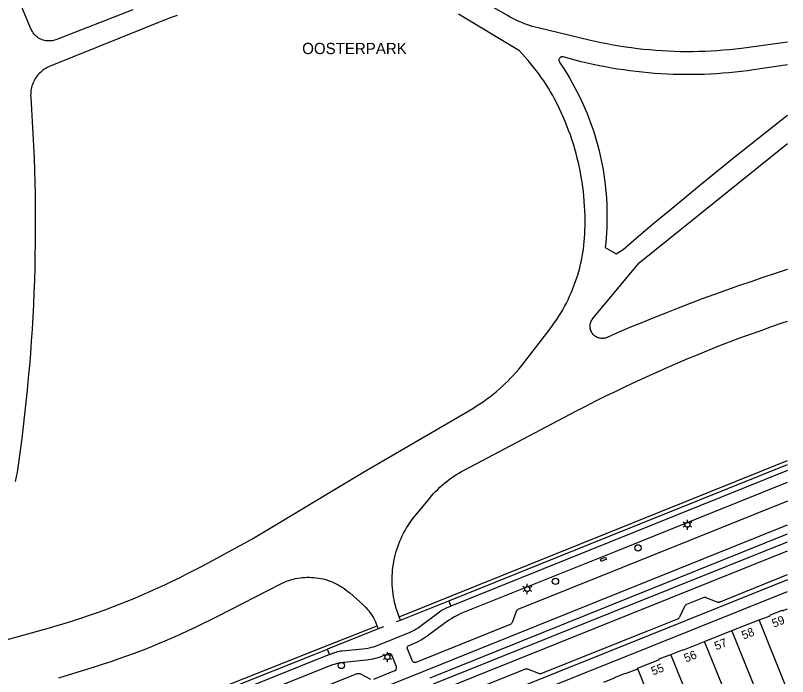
# Model space of a CAD drawing. Extents: x 122462 to 123306, y 485548 to 486417.
# Drawn here: x 123168.9 to 123306, y 485776.1 to 485893.5 of the extents above; entities that cross this region are included whole.
import ezdxf

# ---------------------------------------------------------------- set-up
doc = ezdxf.new("R2010")
doc.units = 0
for name, color, linetype in [('B-WE-IE-MEUBILAIR_WEGMEUBILAIR_VERKEERSBORD-S', 7, 'Continuous'), ('Level 1', 7, 'Continuous'), ('Level 17', 7, 'Continuous'), ('Level 19', 7, 'Continuous'), ('Level 37', 7, 'Continuous'), ('Level 4', 7, 'Continuous'), ('Level 40', 7, 'Continuous'), ('Level 50', 7, 'Continuous'), ('Level 53', 7, 'Continuous'), ('N werkgrens', 7, 'Continuous'), ('N-WE-AL-T25', 7, 'Continuous'), ('N-WE-GR-BOOM_DOORWORTELBARE RUIMTE-G', 7, 'Continuous')]:
    doc.layers.add(name, color=color, linetype=linetype)

msp = doc.modelspace()

# ---------------------------------------------------------------- linework, layer by layer
at = {"layer": 'Level 1'}
msp.add_line((123291.29, 485782.32), (123296.14, 485784.24), dxfattribs=at)
for points in [[(123300.99, 485786.12), (123302.91, 485786.88), (123302.87, 485786.98), (123305.04, 485787.84), (123305.08, 485787.74), (123306.02, 485788.12)], [(123296.14, 485784.24), (123300.98, 485786.15), (123300.99, 485786.12)], [(123285.3, 485780.01), (123287.37, 485780.83), (123287.41, 485780.74), (123291.29, 485782.32)], [(123279.43, 485777.45), (123279.38, 485777.56), (123283.27, 485779.1), (123283.23, 485779.19), (123285.3, 485780.01)], [(123273.37, 485775.07), (123275.3, 485775.83), (123275.26, 485775.92), (123277.21, 485776.69), (123277.25, 485776.6), (123279.43, 485777.45)]]:
    msp.add_lwpolyline(points, dxfattribs=at)
at = {"layer": 'Level 17'}
for p, q in [((123237.27, 485786.09), (123245.85, 485789.52)), ((123245.85, 485789.52), (123246.19, 485788.59)), ((123236.59, 485785.82), (123237.27, 485786.09)), ((123233.31, 485784.52), (123224.29, 485780.91)), ((123234.25, 485784.9), (123233.31, 485784.52)), ((123224.69, 485779.98), (123224.29, 485780.91))]:
    msp.add_line(p, q, dxfattribs=at)
for points in [[(123245.85, 485789.52), (123274.49, 485801.04), (123306.02, 485813.71)], [(123306.02, 485812.64), (123274.86, 485800.11), (123246.19, 485788.59)], [(123239.82, 485778.55), (123239.73, 485778.55), (123239.65, 485778.57), (123239.57, 485778.61), (123239.5, 485778.66), (123239.44, 485778.72), (123239.39, 485778.79), (123238.51, 485780.97), (123238.49, 485781.05), (123238.48, 485781.13), (123238.49, 485781.22), (123238.51, 485781.3), (123238.55, 485781.37), (123238.6, 485781.44), (123238.65, 485781.5), (123238.72, 485781.55), (123238.8, 485781.59), (123239.79, 485781.97), (123240.18, 485782.17), (123240.56, 485782.37), (123240.94, 485782.59), (123241.31, 485782.82), (123241.67, 485783.05), (123242.03, 485783.3), (123245.46, 485785.87), (123245.9, 485786.15), (123246.32, 485786.4), (123246.75, 485786.65), (123247.19, 485786.88), (123247.63, 485787.1), (123248.07, 485787.31), (123275.56, 485798.36), (123306.02, 485810.6)], [(123306.02, 485807.22), (123276.73, 485795.44), (123258.14, 485787.97), (123258.06, 485787.93), (123257.99, 485787.88), (123257.93, 485787.82), (123257.87, 485787.75), (123257.83, 485787.68), (123257.79, 485787.6), (123257.1, 485785.69), (123257.06, 485785.6), (123257, 485785.52), (123256.93, 485785.44), (123256.85, 485785.37), (123256.76, 485785.32), (123239.98, 485778.58), (123239.9, 485778.56), (123239.82, 485778.55)], [(123259.86, 485777.43), (123259.95, 485777.4), (123261.81, 485776.65), (123261.91, 485776.62), (123262.01, 485776.6), (123262.11, 485776.6), (123262.21, 485776.61), (123262.31, 485776.62), (123262.4, 485776.66), (123281.22, 485784.21), (123286.53, 485786.34), (123286.62, 485786.39), (123286.7, 485786.45), (123286.78, 485786.52), (123286.84, 485786.6), (123286.9, 485786.68), (123286.95, 485786.77), (123287.79, 485788.58), (123287.84, 485788.67), (123287.9, 485788.75), (123287.97, 485788.83), (123288.06, 485788.89), (123288.15, 485788.93), (123291.1, 485790.11), (123291.19, 485790.14), (123291.28, 485790.15), (123291.36, 485790.15), (123291.45, 485790.14), (123291.53, 485790.11), (123293.47, 485789.34), (123293.56, 485789.31), (123293.66, 485789.29), (123293.76, 485789.29), (123293.86, 485789.3), (123293.95, 485789.32), (123294.04, 485789.36), (123306.02, 485794.17)], [(123306.02, 485793.23), (123281.54, 485783.41), (123199.54, 485750.48), (123092.05, 485707.28), (123051.43, 485690.97), (123010.46, 485674.56), (123010.38, 485674.54), (123010.31, 485674.53), (123010.23, 485674.54)], [(123010.9, 485672.76), (123016.12, 485674.9), (123023.42, 485677.77), (123052.25, 485689.33), (123092.64, 485705.53), (123175.87, 485738.97), (123200.14, 485748.71), (123282.24, 485781.66), (123306.02, 485791.2)], [(123224.69, 485779.98), (123225.6, 485780.34), (123225.85, 485780.42), (123226.11, 485780.5), (123226.38, 485780.56), (123226.64, 485780.61), (123226.91, 485780.64), (123231.11, 485781.08), (123231.45, 485781.13), (123231.8, 485781.19), (123232.15, 485781.27), (123232.49, 485781.37), (123232.82, 485781.47), (123233.15, 485781.59), (123238.97, 485783.93), (123239.34, 485784.11), (123239.7, 485784.31), (123240.05, 485784.52), (123240.4, 485784.74), (123240.74, 485784.98), (123244.19, 485787.57), (123244.52, 485787.78), (123244.86, 485787.98), (123245.2, 485788.17), (123245.56, 485788.34), (123246.19, 485788.59)], [(123033.3, 485704.16), (123033.55, 485703.56), (123043.09, 485707.71), (123057.87, 485714.13), (123066.6, 485717.66), (123085.63, 485725.38), (123105.66, 485733.48), (123130.67, 485743.46), (123153.55, 485752.61), (123177.38, 485762.27), (123193.41, 485768.64), (123221.97, 485779.99), (123224.29, 485780.91)], [(123224.69, 485779.98), (123193.77, 485767.58)], [(123232.54, 485775.62), (123236.28, 485777.12), (123236.36, 485777.17), (123236.43, 485777.22), (123236.49, 485777.29), (123236.53, 485777.36), (123236.56, 485777.44), (123236.58, 485777.53), (123236.58, 485777.61), (123236.57, 485777.7), (123236.54, 485777.78), (123235.73, 485779.84), (123235.69, 485779.92), (123235.63, 485779.98), (123235.57, 485780.04), (123235.49, 485780.08), (123235.41, 485780.11), (123235.33, 485780.13), (123235.24, 485780.13), (123235.16, 485780.12), (123235.08, 485780.09), (123234.15, 485779.73), (123233.8, 485779.59), (123233.44, 485779.47), (123233.08, 485779.36), (123232.72, 485779.25), (123232.35, 485779.17), (123231.98, 485779.09), (123231.61, 485779.03), (123231.24, 485778.98), (123227.8, 485778.63), (123227.41, 485778.59), (123227.02, 485778.55), (123226.63, 485778.49), (123226.24, 485778.42), (123225.86, 485778.33), (123225.48, 485778.23), (123225.05, 485778.1), (123194.37, 485765.79)], [(123249.16, 485773.29), (123259.37, 485777.38), (123259.47, 485777.42), (123259.56, 485777.44), (123259.66, 485777.45), (123259.76, 485777.44), (123259.86, 485777.43)], [(123195.37, 485762.82), (123229.6, 485776.59), (123229.71, 485776.61), (123229.83, 485776.62), (123229.95, 485776.61), (123230.07, 485776.59), (123230.18, 485776.55), (123231.95, 485775.63)]]:
    msp.add_lwpolyline(points, dxfattribs=at)
at = {"layer": 'Level 19'}
msp.add_line((123237.27, 485786.09), (123237.02, 485786.68), dxfattribs=at)
for points in [[(123306.02, 485888.72), (123297.86, 485887.63), (123296.78, 485887.51), (123295.7, 485887.39), (123294.61, 485887.3), (123293.52, 485887.21), (123292.44, 485887.15), (123291.35, 485887.1), (123290.26, 485887.06), (123289.17, 485887.04), (123288.08, 485887.04), (123286.99, 485887.05), (123285.9, 485887.08), (123284.81, 485887.12), (123283.72, 485887.18), (123282.64, 485887.26), (123281.55, 485887.35), (123280.46, 485887.45), (123279.38, 485887.58), (123278.3, 485887.71), (123277.22, 485887.87), (123276.14, 485888.03), (123275.07, 485888.22), (123274, 485888.42), (123272.93, 485888.63), (123271.87, 485888.86), (123270.8, 485889.11), (123261.71, 485891.28), (123261.19, 485891.41), (123260.68, 485891.55), (123260.17, 485891.71), (123259.66, 485891.88), (123259.16, 485892.07), (123258.66, 485892.27), (123258.17, 485892.48), (123257.69, 485892.7), (123257.21, 485892.94), (123256.73, 485893.19), (123256.27, 485893.46), (123246.28, 485899.29)], [(123174.05, 485889.04), (123173.83, 485889.1), (123173.62, 485889.17), (123173.41, 485889.26), (123173.21, 485889.36), (123173.01, 485889.48), (123172.82, 485889.61), (123172.64, 485889.75), (123172.47, 485889.9), (123172.32, 485890.06), (123172.17, 485890.24), (123172.03, 485890.42), (123171.91, 485890.61), (123171.8, 485890.81), (123171.71, 485891.02), (123170.04, 485894.93), (123169.59, 485894.89), (123169.22, 485898.92)], [(123189.76, 485894.48), (123176.06, 485889.18), (123175.85, 485889.1), (123175.63, 485889.04), (123175.41, 485888.99), (123175.18, 485888.96), (123174.96, 485888.95), (123174.73, 485888.95), (123174.5, 485888.96), (123174.28, 485888.99), (123174.05, 485889.04)], [(123265.08, 485877.81), (123264.68, 485878.57), (123264.32, 485879.24), (123263.94, 485879.91), (123263.54, 485880.56), (123263.14, 485881.21), (123262.72, 485881.85), (123262.28, 485882.48), (123261.84, 485883.1), (123261.38, 485883.72), (123260.91, 485884.32), (123260.43, 485884.91), (123259.94, 485885.5), (123259.43, 485886.07), (123258.91, 485886.64), (123258.39, 485887.19), (123247.56, 485893.72)], [(123197.62, 485893.5), (123196.55, 485893.1), (123195.5, 485892.68), (123175.04, 485884.46), (123174.77, 485884.35), (123174.51, 485884.22), (123174.26, 485884.08), (123174.02, 485883.92), (123173.78, 485883.75), (123173.56, 485883.57), (123173.34, 485883.38), (123173.13, 485883.18), (123172.94, 485882.97), (123172.76, 485882.74), (123172.58, 485882.51), (123172.42, 485882.27), (123172.28, 485882.02), (123172.15, 485881.77), (123172.03, 485881.5), (123171.92, 485881.23), (123171.83, 485880.96), (123171.75, 485880.68), (123171.69, 485880.4), (123171.64, 485880.11), (123171.61, 485879.83), (123171.6, 485879.54), (123171.59, 485879.25), (123171.61, 485878.96), (123171.76, 485876.8), (123171.89, 485874.63), (123172.01, 485872.47)], [(123306.02, 485884.7), (123299.99, 485883.82), (123298.9, 485883.66), (123297.8, 485883.53), (123296.71, 485883.4), (123295.61, 485883.3), (123294.51, 485883.21), (123293.42, 485883.13), (123292.32, 485883.07), (123291.21, 485883.02), (123290.11, 485882.99), (123289.01, 485882.97), (123287.91, 485882.97), (123286.81, 485882.98), (123285.71, 485883.01), (123284.61, 485883.06), (123283.51, 485883.12), (123282.41, 485883.19), (123281.31, 485883.28), (123280.21, 485883.39), (123279.12, 485883.51), (123278.02, 485883.64), (123276.93, 485883.8), (123275.84, 485883.96), (123274.75, 485884.14), (123273.67, 485884.34), (123272.59, 485884.55), (123271.51, 485884.77), (123270.44, 485885.01), (123269.36, 485885.27), (123268.3, 485885.54), (123267.23, 485885.82), (123266.17, 485886.12), (123266.07, 485886.14), (123265.98, 485886.15), (123265.88, 485886.13), (123265.79, 485886.1), (123265.7, 485886.06), (123265.62, 485886.01), (123265.55, 485885.94), (123265.49, 485885.86), (123265.45, 485885.77), (123265.42, 485885.68), (123265.4, 485885.58), (123265.41, 485885.48), (123265.43, 485885.39), (123265.46, 485885.29), (123265.51, 485885.21), (123265.99, 485884.49), (123266.46, 485883.76), (123266.91, 485883.02), (123267.35, 485882.28), (123267.78, 485881.52), (123268.2, 485880.76), (123268.6, 485879.99), (123268.99, 485879.22), (123269.36, 485878.44), (123269.72, 485877.65), (123270.07, 485876.86), (123270.4, 485876.06), (123270.72, 485875.25), (123271.02, 485874.44), (123271.31, 485873.62), (123271.59, 485872.8), (123271.85, 485871.97), (123272.09, 485871.14), (123272.32, 485870.3), (123272.54, 485869.46), (123272.74, 485868.62), (123272.92, 485867.78), (123273.09, 485866.93), (123273.25, 485866.07), (123273.39, 485865.22), (123273.51, 485864.36), (123273.62, 485863.5), (123273.71, 485862.64), (123273.79, 485861.78), (123273.85, 485860.91), (123273.9, 485860.05), (123273.94, 485859.18), (123273.95, 485858.31), (123273.95, 485857.45), (123273.94, 485856.58), (123273.91, 485855.71), (123273.87, 485854.85), (123273.81, 485853.98), (123273.73, 485853.12), (123273.64, 485852.26), (123275.55, 485851.15)], [(123154.79, 485779.15), (123174.92, 485784.73), (123176.32, 485785.13), (123177.72, 485785.55), (123179.11, 485785.98), (123180.5, 485786.43), (123181.89, 485786.9), (123183.26, 485787.38), (123184.64, 485787.87), (123186.01, 485788.38), (123187.37, 485788.91), (123188.73, 485789.45), (123190.08, 485790), (123191.42, 485790.57), (123192.76, 485791.15), (123194.09, 485791.75), (123195.42, 485792.36), (123196.74, 485792.99), (123198.05, 485793.63), (123199.35, 485794.29), (123200.65, 485794.96), (123201.94, 485795.64), (123210.86, 485800.44), (123230.61, 485812.33), (123250.12, 485823.7), (123250.74, 485824.08), (123251.35, 485824.48), (123251.95, 485824.88), (123252.54, 485825.31), (123253.12, 485825.74), (123253.69, 485826.19), (123254.25, 485826.65), (123254.81, 485827.12), (123255.35, 485827.6), (123255.88, 485828.1), (123256.4, 485828.6), (123256.9, 485829.12), (123257.4, 485829.65), (123257.88, 485830.19), (123258.36, 485830.74), (123258.82, 485831.3), (123259.26, 485831.87), (123263.85, 485837.85), (123264.25, 485838.39), (123264.64, 485838.93), (123265.02, 485839.49), (123265.39, 485840.06), (123265.74, 485840.63), (123266.08, 485841.21), (123266.41, 485841.8), (123266.73, 485842.39), (123267.03, 485843), (123267.31, 485843.61), (123267.59, 485844.22), (123267.85, 485844.84), (123268.09, 485845.47), (123268.32, 485846.1), (123268.54, 485846.74), (123268.75, 485847.38), (123268.93, 485848.03), (123269.11, 485848.68), (123269.27, 485849.33), (123269.41, 485849.99), (123269.54, 485850.65), (123269.66, 485851.31), (123269.76, 485851.98), (123269.84, 485852.65), (123269.91, 485853.32), (123269.97, 485853.99), (123270.01, 485854.66), (123270.03, 485855.33), (123270.05, 485856.19), (123270.06, 485857.06), (123270.05, 485857.92), (123270.02, 485858.78), (123269.98, 485859.64), (123269.92, 485860.5), (123269.84, 485861.36), (123269.75, 485862.21), (123269.64, 485863.07), (123269.52, 485863.92), (123269.38, 485864.77), (123269.23, 485865.62), (123269.06, 485866.46), (123268.87, 485867.3), (123268.67, 485868.14), (123268.46, 485868.97), (123268.22, 485869.8), (123267.98, 485870.63), (123267.71, 485871.45), (123267.44, 485872.26), (123267.14, 485873.07), (123266.84, 485873.88), (123266.51, 485874.68), (123266.18, 485875.47), (123265.83, 485876.26), (123265.46, 485877.04), (123265.08, 485877.81)], [(123275.55, 485851.15), (123276.8, 485851.92), (123279.57, 485854.28), (123282.35, 485856.63), (123285.15, 485858.96), (123287.95, 485861.28), (123290.76, 485863.6), (123293.58, 485865.89), (123296.42, 485868.18), (123299.26, 485870.45), (123302.11, 485872.72), (123304.97, 485874.97), (123306.02, 485875.78)], [(123172.01, 485872.47), (123172.12, 485870.3), (123172.21, 485868.13), (123172.28, 485865.97), (123172.34, 485863.8), (123172.38, 485861.63), (123172.41, 485859.46), (123172.42, 485857.29), (123172.42, 485855.12), (123172.4, 485852.95), (123172.36, 485850.78), (123172.31, 485848.62), (123172.25, 485846.45), (123172.17, 485844.28), (123172.07, 485842.11), (123171.96, 485839.95), (123171.84, 485837.78), (123171.7, 485835.62), (123171.54, 485833.45), (123171.37, 485831.29), (123171.18, 485829.13), (123170.98, 485826.97), (123170.76, 485824.81), (123170.53, 485822.66), (123170.28, 485820.5), (123170.01, 485818.35), (123169.73, 485816.2), (123169.44, 485814.05), (123169.31, 485813.21), (123169.17, 485812.37), (123169.01, 485811.54), (123168.84, 485810.71)], [(123273.08, 485836.12), (123272.9, 485836.13), (123272.73, 485836.16), (123272.55, 485836.19), (123272.38, 485836.25), (123272.21, 485836.31), (123272.05, 485836.4), (123271.9, 485836.49), (123271.75, 485836.6), (123271.62, 485836.72), (123271.49, 485836.84), (123271.38, 485836.98), (123271.28, 485837.13), (123271.19, 485837.29), (123271.11, 485837.45), (123271.05, 485837.62), (123271, 485837.79), (123270.97, 485837.97), (123270.95, 485838.15), (123270.95, 485838.33), (123270.96, 485838.51), (123270.99, 485838.69), (123271.03, 485838.86), (123271.09, 485839.03), (123271.16, 485839.2), (123271.24, 485839.36), (123271.34, 485839.51), (123271.45, 485839.65), (123279.69, 485849.52), (123306.02, 485870.76)], [(123306.02, 485848.35), (123305.97, 485848.34), (123303.8, 485847.64), (123301.64, 485846.93), (123299.47, 485846.2), (123297.32, 485845.46), (123295.16, 485844.7), (123293.02, 485843.93), (123290.88, 485843.14), (123288.74, 485842.34), (123286.61, 485841.52), (123284.49, 485840.69), (123282.37, 485839.84), (123280.26, 485838.98), (123278.15, 485838.1), (123276.05, 485837.21), (123273.96, 485836.3), (123273.79, 485836.24), (123273.62, 485836.19), (123273.44, 485836.15), (123273.26, 485836.13), (123273.08, 485836.12)], [(123237.02, 485786.68), (123236.84, 485787.18), (123236.67, 485787.68), (123236.51, 485788.18), (123236.37, 485788.7), (123236.24, 485789.21), (123236.13, 485789.73), (123236.03, 485790.25), (123235.95, 485790.77), (123235.89, 485791.3), (123235.84, 485791.82), (123235.81, 485792.35), (123235.79, 485792.88), (123235.79, 485793.41), (123235.8, 485793.94), (123235.83, 485794.47), (123235.87, 485794.99), (123235.93, 485795.52), (123236.01, 485796.05), (123236.1, 485796.57), (123236.21, 485797.09), (123236.33, 485797.6), (123236.46, 485798.11), (123236.62, 485798.62), (123236.78, 485799.12), (123236.96, 485799.62), (123237.16, 485800.11), (123237.37, 485800.6), (123237.6, 485801.08), (123237.83, 485801.55), (123238.09, 485802.01), (123238.35, 485802.47), (123238.63, 485802.92), (123238.93, 485803.36), (123239.23, 485803.79), (123239.55, 485804.22), (123239.88, 485804.63), (123242.46, 485807.76), (123242.81, 485808.17), (123243.16, 485808.56), (123243.52, 485808.95), (123243.9, 485809.32), (123244.28, 485809.69), (123244.67, 485810.04), (123245.07, 485810.39), (123245.48, 485810.72), (123245.9, 485811.05), (123246.33, 485811.36), (123246.77, 485811.66), (123247.21, 485811.95), (123247.66, 485812.22), (123248.12, 485812.49), (123248.59, 485812.74), (123268.43, 485823.18), (123270.2, 485824.1), (123271.98, 485825.01), (123273.76, 485825.9), (123275.55, 485826.78), (123277.35, 485827.65), (123279.15, 485828.5), (123280.97, 485829.33), (123282.79, 485830.15), (123284.61, 485830.96), (123286.44, 485831.75), (123288.28, 485832.53), (123290.12, 485833.29), (123291.97, 485834.04), (123293.83, 485834.78), (123295.69, 485835.49), (123297.56, 485836.2), (123299.43, 485836.89), (123301.31, 485837.56), (123303.19, 485838.22), (123305.08, 485838.87), (123306.02, 485839.18)], [(123176.62, 485775.82), (123179.88, 485776.83), (123183.13, 485777.85), (123184.52, 485778.3), (123185.92, 485778.77), (123187.3, 485779.25), (123188.68, 485779.74), (123190.06, 485780.25), (123191.43, 485780.78), (123192.8, 485781.31), (123194.16, 485781.87), (123195.51, 485782.43), (123196.86, 485783.01), (123198.2, 485783.61), (123199.54, 485784.22), (123200.87, 485784.84), (123202.19, 485785.48), (123203.51, 485786.13), (123204.82, 485786.79), (123215.9, 485792.49), (123216.27, 485792.67), (123216.65, 485792.84), (123217.04, 485793), (123217.43, 485793.14), (123217.82, 485793.26), (123218.22, 485793.37), (123218.62, 485793.46), (123219.03, 485793.54), (123219.44, 485793.61), (123219.85, 485793.66), (123220.26, 485793.69), (123220.67, 485793.71), (123221.09, 485793.71), (123221.5, 485793.69), (123221.91, 485793.67), (123222.32, 485793.62), (123222.73, 485793.56), (123223.14, 485793.49), (123223.54, 485793.4), (123223.94, 485793.29), (123224.34, 485793.17), (123224.73, 485793.03), (123225.12, 485792.88), (123225.49, 485792.72), (123225.87, 485792.54), (123226.23, 485792.35), (123226.59, 485792.14), (123226.94, 485791.92)], [(123226.94, 485791.92), (123227.29, 485791.69), (123227.62, 485791.44), (123227.94, 485791.19), (123228.26, 485790.92), (123230.58, 485788.84), (123230.86, 485788.58), (123231.13, 485788.31), (123231.38, 485788.03), (123231.63, 485787.74), (123231.86, 485787.44), (123232.08, 485787.12), (123232.29, 485786.8), (123232.48, 485786.48), (123232.67, 485786.14), (123232.83, 485785.8), (123232.98, 485785.45), (123233.12, 485785.09)], [(123233.12, 485785.09), (123233.22, 485784.81), (123233.31, 485784.52)]]:
    msp.add_lwpolyline(points, dxfattribs=at)
at = {"layer": 'Level 37'}
for points in [[(123051.53, 485700.77), (123241.71, 485777.16), (123306.02, 485803.04)], [(123242.53, 485775.87), (123306.02, 485801.43)], [(123243.14, 485774.75), (123306.02, 485800.02)], [(123243.94, 485773.45), (123306.02, 485798.41)]]:
    msp.add_lwpolyline(points, dxfattribs=at)
at = {"layer": 'Level 4'}
for p, q in [((123306.02, 485773.61), (123300.99, 485786.12)), ((123296.02, 485770.54), (123291.29, 485782.32)), ((123290.06, 485768.15), (123285.3, 485780.01)), ((123284.12, 485765.76), (123279.43, 485777.45))]:
    msp.add_line(p, q, dxfattribs=at)
at = {"layer": 'Level 40'}
msp.add_lwpolyline([(123272.92, 485796.52), (123272.77, 485796.89), (123273.69, 485797.28), (123273.84, 485796.91), (123272.92, 485796.52)], dxfattribs=at)
at = {"layer": 'Level 50'}
for p, q in [((123287.85, 485803.26), (123287.46, 485803.48)), ((123288.24, 485803.48), (123288.24, 485803.93)), ((123289.02, 485803.48), (123288.63, 485803.26)), ((123287.85, 485802.81), (123287.46, 485802.58)), ((123288.24, 485802.13), (123288.24, 485802.58)), ((123289.02, 485802.58), (123288.63, 485802.81)), ((123259.41, 485791.84), (123259.02, 485792.06)), ((123259.8, 485792.06), (123259.8, 485792.51)), ((123260.58, 485792.06), (123260.19, 485791.84)), ((123259.41, 485791.39), (123259.02, 485791.16)), ((123259.8, 485790.71), (123259.8, 485791.16)), ((123260.58, 485791.16), (123260.19, 485791.39)), ((123234.57, 485779.74), (123234.18, 485779.97)), ((123234.96, 485779.97), (123234.96, 485780.42)), ((123235.74, 485779.97), (123235.35, 485779.74)), ((123234.57, 485779.29), (123234.18, 485779.07)), ((123234.96, 485778.62), (123234.96, 485779.07)), ((123235.74, 485779.07), (123235.35, 485779.29))]:
    msp.add_line(p, q, dxfattribs=at)
for centre in [(123288.24, 485803.03), (123259.8, 485791.61), (123234.96, 485779.52)]:
    msp.add_circle(centre, 0.45, dxfattribs=at)
at = {"layer": 'Level 53'}
for centre in [(123279.46, 485798.92), (123264.8, 485792.98), (123226.78, 485778.03)]:
    msp.add_circle(centre, 0.56, dxfattribs=at)
at = {"layer": 'N werkgrens'}
msp.add_line((123237.02, 485786.68), (123306.02, 485814.42), dxfattribs=at)
msp.add_lwpolyline([(123033.3, 485704.16), (123057.62, 485714.73), (123066.35, 485718.26), (123085.38, 485725.98), (123105.42, 485734.09), (123130.43, 485744.07), (123153.31, 485753.22), (123177.14, 485762.88), (123221.73, 485780.6), (123233.12, 485785.09)], dxfattribs=at)
at = {"layer": 'N-WE-AL-T25'}
msp.add_line((123301.27, 485771.46), (123296.14, 485784.24), dxfattribs=at)

# ---------------------------------------------------------------- texts
at = {"layer": 'B-WE-IE-MEUBILAIR_WEGMEUBILAIR_VERKEERSBORD-S'}
for s, p in [('59', (123303.59, 485784.74)), ('58', (123298.2, 485782.62)), ('57', (123293.37, 485780.72)), ('56', (123287.98, 485778.56)), ('55', (123282.14, 485776.24))]:
    msp.add_text(s, height=1.5, rotation=21.512, dxfattribs=at).set_placement(p)
at = {"layer": 'N-WE-GR-BOOM_DOORWORTELBARE RUIMTE-G'}
msp.add_text('OOSTERPARK', height=2, dxfattribs=at).set_placement((123219.82, 485886.62))

doc.saveas('drawing.dxf')
